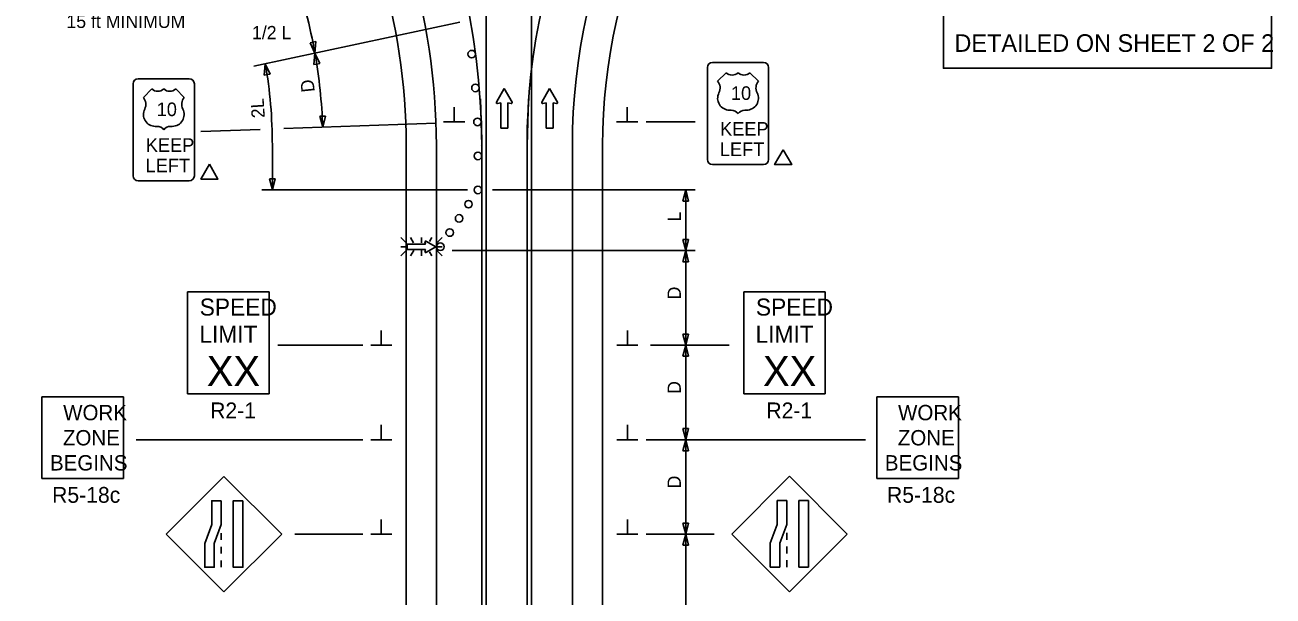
# Model space of a CAD drawing. Extents: x 16562 to 18475, y 6979 to 8243.
# Drawn here: x 16752 to 17413, y 7561 to 7863 of the extents above; entities that cross this region are included whole.
import ezdxf

# ---------------------------------------------------------------- set-up
doc = ezdxf.new("R2010")
doc.units = 0
for name, color, linetype in [('ALI_LEGAL_EX', 7, 'Continuous'), ('MT_SCRATCH_LEVEL_E', 7, 'Continuous'), ('PAVT_EDGE_EX', 7, 'Continuous'), ('TRAFFIC_SIGNS_PR', 7, 'Continuous'), ('TYPICAL_EX', 7, 'Continuous'), ('TYPICAL_TEXT_DIMEN_EX', 7, 'Continuous'), ('TYPICAL_TEXT_DIMEN_PR', 7, 'Continuous')]:
    doc.layers.add(name, color=color, linetype=linetype)

msp = doc.modelspace()

# ---------------------------------------------------------------- linework, layer by layer
at = {"layer": 'ALI_LEGAL_EX'}
for p, q in [((16995.95, 8243.16), (16995.95, 7428.9)), ((17019.95, 8243.16), (17019.95, 7428.9)), ((16993.65, 7372.88), (16993.65, 7799.18)), ((17017.65, 7372.88), (17017.65, 7799.18))]:
    msp.add_line(p, q, dxfattribs=at)
for points in [[(16993.6, 7798.84), (16993.65, 7799.18), (16993.08, 7823.83)], [(17017.7, 7798.84), (17017.65, 7799.18), (17018.48, 7823.82)], [(16993.65, 7698.83), (16993.65, 7723.83)], [(17017.65, 7698.83), (17017.65, 7723.83)], [(16993.65, 7598.83), (16993.65, 7623.83)], [(17017.65, 7598.83), (17017.65, 7623.83)]]:
    msp.add_lwpolyline(points, dxfattribs=at)
for centre, radius, start, end in [((16629.65, 7799.18), 364, 0, 57.29578), ((17357.65, 7799.18), 340, 129.56655, 180)]:
    msp.add_arc(centre, radius, start, end, dxfattribs=at)
at = {"layer": 'MT_SCRATCH_LEVEL_E'}
for p, q in [((17005.57, 7829.24), (17001.46, 7822)), ((17009.72, 7822), (17005.57, 7829.24)), ((17029.62, 7829.24), (17025.51, 7822)), ((17033.77, 7822), (17029.62, 7829.24)), ((17001.94, 7821.32), (17003.72, 7821.63)), ((17003.72, 7821.63), (17003.72, 7808.37)), ((17007.46, 7808.37), (17007.46, 7821.63)), ((17007.46, 7821.63), (17009.24, 7821.32)), ((17025.99, 7821.32), (17027.77, 7821.63)), ((17027.77, 7821.63), (17027.77, 7808.37)), ((17031.51, 7808.37), (17031.51, 7821.63)), ((17031.51, 7821.63), (17033.29, 7821.32)), ((17003.72, 7808.37), (17007.46, 7808.37)), ((17027.77, 7808.37), (17031.51, 7808.37))]:
    msp.add_line(p, q, dxfattribs=at)
for centre, start, end in [((17001.87, 7821.78), 150.42484, 279.96381), ((17009.31, 7821.78), 260.03619, 29.77312), ((17025.92, 7821.78), 150.42484, 279.96381), ((17033.36, 7821.78), 260.03619, 29.77312)]:
    msp.add_arc(centre, 0.463, start, end, dxfattribs=at)
at = {"layer": 'PAVT_EDGE_EX'}
for p, q in [((16953.65, 7799.18), (16953.65, 7372.88)), ((16969.65, 7799.18), (16969.65, 7372.88)), ((17041.65, 7799.18), (17041.65, 7372.88)), ((17057.65, 7799.18), (17057.65, 7372.88))]:
    msp.add_line(p, q, dxfattribs=at)
for centre, radius, start, end in [((16629.65, 7799.18), 340, 0, 67.69076), ((16629.65, 7799.18), 324, 0, 67.83913), ((17357.65, 7799.18), 316, 129.56655, 180), ((17357.65, 7799.18), 300, 129.56655, 180), ((17357.65, 7799.18), 300, 180, 180.00000277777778)]:
    msp.add_arc(centre, radius, start, end, dxfattribs=at)
at = {"layer": 'TRAFFIC_SIGNS_PR'}
for p, q in [((17142.86, 7843.05), (17115.86, 7843.05)), ((17113.16, 7840.35), (17113.16, 7791.75)), ((17145.56, 7791.75), (17145.56, 7840.35)), ((16809.15, 7831.77), (16809.15, 7783.17)), ((16838.85, 7834.47), (16811.85, 7834.47)), ((16841.55, 7783.17), (16841.55, 7831.77)), ((17115.86, 7789.05), (17142.86, 7789.05)), ((16811.85, 7780.47), (16838.85, 7780.47)), ((16953.72, 7747.59), (16950.9, 7750.41)), ((16956.02, 7750.41), (16957.64, 7747.59)), ((16961.8, 7747.59), (16961.8, 7750.41)), ((16967.27, 7750.41), (16966.07, 7748.32)), ((16972.71, 7750.41), (16969.89, 7747.59)), ((16953.72, 7745.56), (16950.9, 7745.56)), ((16969.89, 7745.56), (16972.71, 7745.56)), ((16953.72, 7743.53), (16950.9, 7740.7)), ((16957.67, 7743.53), (16956.04, 7740.71)), ((16961.8, 7743.53), (16961.8, 7740.71)), ((16965.99, 7742.89), (16967.25, 7740.71)), ((16972.71, 7740.71), (16969.89, 7743.53)), ((16837.89, 7721.7), (16881.09, 7721.7)), ((16837.89, 7667.7), (16837.89, 7721.7)), ((16881.09, 7667.7), (16881.09, 7721.7)), ((17132.35, 7721.7), (17175.55, 7721.7)), ((17132.35, 7667.7), (17132.35, 7721.7)), ((17175.55, 7667.7), (17175.55, 7721.7)), ((16760.83, 7623), (16760.83, 7666.2)), ((16760.83, 7666.2), (16804.03, 7666.2)), ((16804.03, 7623), (16804.03, 7666.2)), ((16837.89, 7667.7), (16881.09, 7667.7)), ((17132.35, 7667.7), (17175.55, 7667.7)), ((17202.81, 7623), (17202.81, 7666.2)), ((17202.81, 7666.2), (17246.01, 7666.2)), ((17246.01, 7623), (17246.01, 7666.2)), ((16760.83, 7623), (16804.03, 7623)), ((16857.22, 7624.05), (16826.68, 7593.5)), ((16887.77, 7593.5), (16857.22, 7624.05)), ((17156.61, 7624.16), (17126.06, 7593.61)), ((17187.15, 7593.61), (17156.61, 7624.16)), ((17202.81, 7623), (17246.01, 7623)), ((16826.68, 7593.5), (16857.22, 7562.96)), ((16855.82, 7594.06), (16855.82, 7590.46)), ((16857.22, 7562.96), (16887.77, 7593.5)), ((17126.06, 7593.61), (17156.61, 7563.06)), ((17155.2, 7594.16), (17155.2, 7590.56)), ((17156.61, 7563.06), (17187.15, 7593.61)), ((16855.82, 7586.86), (16855.82, 7583.26)), ((17155.2, 7586.96), (17155.2, 7583.36)), ((16855.82, 7579.66), (16855.82, 7576.06)), ((17155.2, 7579.76), (17155.2, 7576.16))]:
    msp.add_line(p, q, dxfattribs=at)
for points in [[(16963.63, 7748.24), (16963.86, 7746.94), (16954.14, 7746.94), (16954.14, 7744.2), (16963.86, 7744.2), (16963.63, 7742.9)], [(16964.13, 7742.54), (16969.44, 7745.56), (16964.13, 7748.6)]]:
    msp.add_lwpolyline(points, dxfattribs=at)
for points in [[(16855.82, 7611.21), (16855.82, 7598.63), (16852.06, 7588.63), (16852.06, 7576.06), (16847, 7576.06), (16847, 7588.63), (16850.77, 7598.63), (16850.77, 7611.21)], [(16867.22, 7611.21), (16867.22, 7576.06), (16862.17, 7576.06), (16862.17, 7611.21)], [(17155.2, 7611.31), (17155.2, 7598.74), (17151.44, 7588.74), (17151.44, 7576.16), (17146.39, 7576.16), (17146.39, 7588.74), (17150.15, 7598.74), (17150.15, 7611.31)], [(17166.61, 7611.31), (17166.61, 7576.16), (17161.55, 7576.16), (17161.55, 7611.31)]]:
    msp.add_lwpolyline(points, close=True, dxfattribs=at)
for centre in [(16988.39, 7847.48), (16990.36, 7829.59), (16991.42, 7811.62), (16991.64, 7793.62), (16991.64, 7775.62), (16991.64, 7775.62), (16986.67, 7768.11), (16981.7, 7760.61), (16976.73, 7753.1), (16971.76, 7745.6)]:
    msp.add_circle(centre, 2, dxfattribs=at)
for centre, radius, start, end in [((17115.86, 7840.35), 2.7, 90, 180), ((17142.86, 7840.35), 2.7, 0, 90), ((16811.85, 7831.77), 2.7, 90, 180), ((16838.85, 7831.77), 2.7, 0, 90), ((17115.86, 7791.75), 2.7, 180, 270), ((17142.86, 7791.75), 2.7, 270, 0), ((16811.85, 7783.17), 2.7, 180, 270), ((16838.85, 7783.17), 2.7, 270, 0), ((16963.97, 7748.3), 0.341, 61.48329, 189.95933), ((16963.97, 7742.84), 0.341, 170.73078, 298.89165)]:
    msp.add_arc(centre, radius, start, end, dxfattribs=at)
at = {"layer": 'TYPICAL_EX'}
for p, q in [((17118.56, 7833.15), (17123.06, 7837.65)), ((17140.16, 7833.15), (17135.66, 7837.65)), ((16814.55, 7824.57), (16819.05, 7829.07)), ((16836.15, 7824.57), (16831.65, 7829.07)), ((17124.85, 7817.84), (17125.75, 7817.84)), ((17133.86, 7817.84), (17132.96, 7817.84)), ((16820.84, 7809.26), (16821.74, 7809.26)), ((16829.85, 7809.26), (16828.95, 7809.26))]:
    msp.add_line(p, q, dxfattribs=at)
for centre, radius, start, end in [((17126.21, 7840.93), 4.55, 226.14041, 313.85958), ((17132.51, 7840.93), 4.55, 226.14042, 313.85959), ((17114.29, 7829.55), 5.58, 333.09768, 40.19361), ((17144.42, 7829.55), 5.58, 139.80639, 206.90233), ((16810.28, 7820.97), 5.58, 333.09768, 40.19361), ((16822.2, 7832.35), 4.55, 226.14041, 313.85958), ((16828.5, 7832.35), 4.55, 226.14042, 313.85959), ((16840.41, 7820.97), 5.58, 139.80639, 206.90233), ((17124.86, 7824.13), 6.29, 152.6698, 269.90132), ((17133.85, 7824.13), 6.29, 270.09868, 27.3302), ((16820.85, 7815.55), 6.29, 152.6698, 269.90132), ((16829.84, 7815.55), 6.29, 270.09868, 27.3302), ((17125.76, 7813.33), 4.51, 37.1038, 90.13853), ((17132.95, 7813.33), 4.51, 89.86147, 142.8962), ((16821.75, 7804.75), 4.51, 37.1038, 90.13853), ((16828.94, 7804.75), 4.51, 89.86147, 142.8962)]:
    msp.add_arc(centre, radius, start, end, dxfattribs=at)
at = {"layer": 'TYPICAL_TEXT_DIMEN_EX'}
msp.add_lwpolyline([(17238.13, 7930.32), (17411.78, 7930.32), (17411.78, 7839.99), (17238.13, 7839.99)], close=True, dxfattribs=at)
at = {"layer": 'TYPICAL_TEXT_DIMEN_PR'}
for p, q in [((16872.98, 7841.11), (16982.07, 7864.4)), ((16902.79, 7853.52), (16904.33, 7853.8)), ((16905.36, 7848.02), (16902.79, 7853.52)), ((16904.33, 7853.8), (16905.88, 7854.07)), ((16905.88, 7854.07), (16905.36, 7848.02)), ((16904.83, 7841.98), (16905.36, 7848.02)), ((16905.36, 7848.02), (16907.92, 7842.53)), ((16878.58, 7836.38), (16879.11, 7842.42)), ((16880.13, 7836.65), (16878.58, 7836.38)), ((16879.11, 7842.42), (16881.67, 7836.92)), ((16881.67, 7836.92), (16880.13, 7836.65)), ((16906.38, 7842.25), (16904.83, 7841.98)), ((16907.92, 7842.53), (16906.38, 7842.25)), ((16979.13, 7811.58), (16979.13, 7819.36)), ((17070.66, 7811.58), (17070.66, 7819.36)), ((16888.94, 7808.12), (16969.45, 7810.89)), ((16909.48, 7808.82), (16907.91, 7814.69)), ((16907.91, 7814.69), (16909.48, 7814.69)), ((16909.48, 7814.69), (16911.05, 7814.69)), ((16911.05, 7814.69), (16909.48, 7808.82)), ((16984.75, 7811.58), (16973.5, 7811.58)), ((17076.29, 7811.58), (17065.04, 7811.58)), ((17080.65, 7811.58), (17106.65, 7811.58)), ((16845.01, 7806.6), (16876.45, 7807.69)), ((16882.83, 7799.18), (16882.83, 7775.62)), ((16882.83, 7775.62), (16881.26, 7781.49)), ((16881.26, 7781.49), (16882.83, 7781.49)), ((16882.83, 7781.49), (16884.4, 7781.49)), ((16884.4, 7781.49), (16882.83, 7775.62)), ((16986.15, 7775.62), (16877.28, 7775.62)), ((16999.42, 7775.62), (17106.65, 7775.62)), ((17100.08, 7769.76), (17101.65, 7775.62)), ((17101.65, 7775.62), (17101.65, 7743.52)), ((17101.65, 7775.62), (17103.22, 7769.76)), ((17101.65, 7769.76), (17100.08, 7769.76)), ((17103.22, 7769.76), (17101.65, 7769.76)), ((17101.65, 7743.52), (17100.08, 7749.38)), ((17100.08, 7749.38), (17101.65, 7749.38)), ((17101.65, 7749.38), (17103.22, 7749.38)), ((17103.22, 7749.38), (17101.65, 7743.52)), ((16978.05, 7743.52), (17106.65, 7743.52)), ((17100.08, 7737.66), (17101.65, 7743.52)), ((17101.65, 7737.66), (17100.08, 7737.66)), ((17101.65, 7743.52), (17101.65, 7693.52)), ((17101.65, 7743.52), (17103.22, 7737.66)), ((17101.65, 7743.52), (17101.65, 7693.52)), ((17103.22, 7737.66), (17101.65, 7737.66)), ((16940.52, 7693.52), (16940.52, 7701.31)), ((17070.77, 7693.52), (17070.77, 7701.31)), ((17101.65, 7693.52), (17100.08, 7699.38)), ((17100.08, 7699.38), (17101.65, 7699.38)), ((17101.65, 7699.38), (17103.22, 7699.38)), ((17103.22, 7699.38), (17101.65, 7693.52)), ((16914.8, 7693.52), (16885.77, 7693.52)), ((16930.65, 7693.52), (16904.65, 7693.52)), ((16934.9, 7693.52), (16946.15, 7693.52)), ((17076.4, 7693.52), (17065.15, 7693.52)), ((17083.01, 7693.52), (17124.67, 7693.52)), ((17100.08, 7687.66), (17101.65, 7693.52)), ((17101.65, 7693.52), (17101.65, 7643.52)), ((17101.65, 7693.52), (17103.22, 7687.66)), ((17101.65, 7687.66), (17100.08, 7687.66)), ((17103.22, 7687.66), (17101.65, 7687.66)), ((16940.52, 7643.52), (16940.52, 7651.31)), ((17070.77, 7643.52), (17070.77, 7651.31)), ((17101.65, 7643.52), (17100.08, 7649.38)), ((17100.08, 7649.38), (17101.65, 7649.38)), ((17101.65, 7649.38), (17103.22, 7649.38)), ((17103.22, 7649.38), (17101.65, 7643.52)), ((16907.46, 7643.52), (16810.76, 7643.52)), ((16930.65, 7643.52), (16904.65, 7643.52)), ((16934.9, 7643.52), (16946.15, 7643.52)), ((17076.4, 7643.52), (17065.15, 7643.52)), ((17080.65, 7643.52), (17106.65, 7643.52)), ((17100.08, 7637.66), (17101.65, 7643.52)), ((17101.65, 7643.52), (17101.65, 7593.52)), ((17101.65, 7643.52), (17103.22, 7637.66)), ((17106.65, 7643.52), (17196.9, 7643.52)), ((17101.65, 7637.66), (17100.08, 7637.66)), ((17103.22, 7637.66), (17101.65, 7637.66)), ((16940.52, 7593.52), (16940.52, 7601.31)), ((17070.77, 7593.52), (17070.77, 7601.31)), ((17101.65, 7593.52), (17100.08, 7599.38)), ((17100.08, 7599.38), (17101.65, 7599.38)), ((17101.65, 7599.38), (17103.22, 7599.38)), ((17103.22, 7599.38), (17101.65, 7593.52)), ((16930.65, 7593.52), (16894.65, 7593.52)), ((16934.9, 7593.52), (16946.15, 7593.52)), ((17076.4, 7593.52), (17065.15, 7593.52)), ((17080.65, 7593.52), (17116.65, 7593.52)), ((17100.08, 7587.66), (17101.65, 7593.52)), ((17101.65, 7593.52), (17101.65, 7493.52)), ((17101.65, 7593.52), (17103.22, 7587.66)), ((17101.65, 7587.66), (17100.08, 7587.66)), ((17103.22, 7587.66), (17101.65, 7587.66))]:
    msp.add_line(p, q, dxfattribs=at)
for points in [[(17153.27, 7796.91), (17148.74, 7789.07), (17157.8, 7789.07)], [(16849.5, 7789.19), (16844.98, 7781.35), (16854.03, 7781.35)]]:
    msp.add_lwpolyline(points, close=True, dxfattribs=at)
for radius, start, end in [(280, 10.04609, 14.46289), (280, 1.97339, 10.04601), (253.18, 0, 9.83395)]:
    msp.add_arc((16629.65, 7799.18), radius, start, end, dxfattribs=at)

# ---------------------------------------------------------------- texts
at = {"layer": 'TRAFFIC_SIGNS_PR'}
for s, height, p in [('10', 7.2, (17125.6, 7823.25)), ('10', 7.2, (16821.59, 7814.67)), ('KEEP', 7.2, (17119.84, 7804.35)), ('KEEP', 7.2, (16815.82, 7795.77)), ('LEFT', 7.2, (17119.74, 7793.55)), ('LEFT', 7.2, (16815.73, 7784.97)), ('SPEED', 9, (16844.38, 7709.17)), ('SPEED', 9, (17138.83, 7709.17)), ('LIMIT', 9, (16844.19, 7694.77)), ('LIMIT', 9, (17138.65, 7694.77)), ('XX', 15.785, (16848.14, 7671.93)), ('XX', 15.785, (17142.6, 7671.93)), ('WORK', 8.119, (16772.08, 7653.79)), ('R2-1', 8.37, (16849.9, 7654.83)), ('R2-1', 8.37, (17144.36, 7654.83)), ('WORK', 8.119, (17214.06, 7653.79)), ('ZONE', 8.119, (16771.95, 7640.5)), ('ZONE', 8.119, (17213.93, 7640.5)), ('BEGINS', 8.119, (16765.12, 7627.22)), ('BEGINS', 8.119, (17207.1, 7627.22)), ('R5-18c', 8.37, (16766.24, 7610.13)), ('R5-18c', 8.37, (17208.22, 7610.13))]:
    msp.add_text(s, height=height, dxfattribs=at).set_placement(p)
at = {"layer": 'TYPICAL_TEXT_DIMEN_EX'}
msp.add_text('DETAILED ON SHEET 2 OF 2', height=9.3, dxfattribs=at).set_placement((17243.9, 7848.69))
at = {"layer": 'TYPICAL_TEXT_DIMEN_PR'}
for s, p in [('15 ft MINIMUM', (16773.82, 7861.31)), ('1/2 L', (16872.05, 7855.38))]:
    msp.add_text(s, height=7, dxfattribs=at).set_placement(p)
for s, rotation, p in [('D', 96.00984, (16905.29, 7827.65)), ('2L', 93.80159, (16878.89, 7813.87)), ('L', 90, (17099.09, 7758.93)), ('D', 90, (17099.09, 7717.74)), ('D', 90, (17099.09, 7667.74)), ('D', 90, (17099.09, 7617.74))]:
    msp.add_text(s, height=7, rotation=rotation, dxfattribs=at).set_placement(p)

doc.saveas('drawing.dxf')
